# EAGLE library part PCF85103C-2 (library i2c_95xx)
256 x 8-Bit CMOS EEPROM with I²C Bus Interface
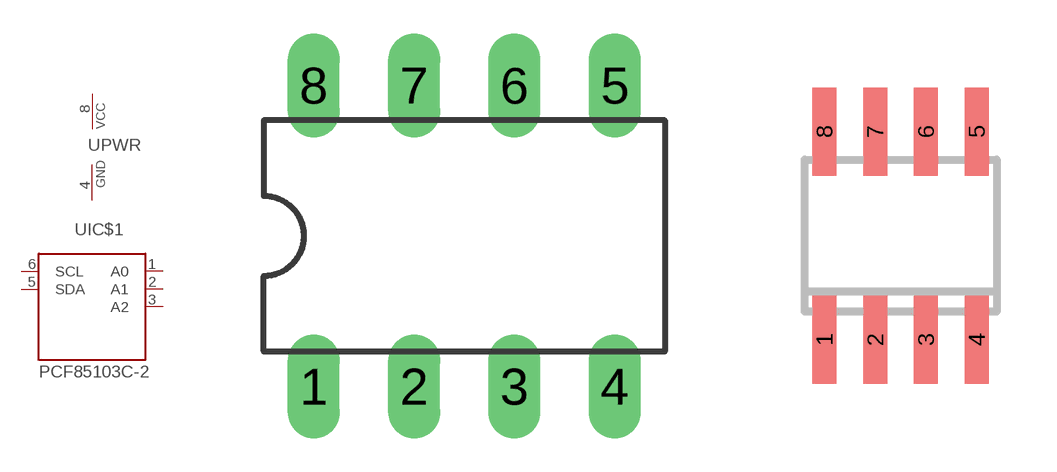
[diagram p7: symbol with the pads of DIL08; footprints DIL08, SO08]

Designator prefix -; gates IC$1=PCF85103 PWR=PWRN

## PCF85103C-2P/00  [DIL08]
1  IC$1:A0  in
2  IC$1:A1  in
3  IC$1:A2  in
4  PWR:GND  pwr
5  IC$1:SDA
6  IC$1:SCL  in
8  PWR:VCC  pwr

## PCF85103C-2T/00  [SO08]
Pads as for DIL08

## Footprint DIL08 (pad centres in mm)
drill 0.813 long: 1 -3.81,-3.81; 2 -1.27,-3.81; 3 1.27,-3.81; 4 3.81,-3.81; 5 3.81,3.81; 6 1.27,3.81; 7 -1.27,3.81; 8 -3.81,3.81

## Footprint SO08 (pad centres in mm)
smd 0.6 x 2.2: 1 -1.905,-2.6; 2 -0.635,-2.6; 3 0.635,-2.6; 4 1.905,-2.6; 5 1.905,2.6; 6 0.635,2.6; 7 -0.635,2.6; 8 -1.905,2.6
